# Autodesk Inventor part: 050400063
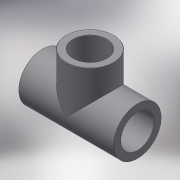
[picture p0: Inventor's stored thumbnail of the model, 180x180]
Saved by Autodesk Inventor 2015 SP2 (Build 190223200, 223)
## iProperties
Created: 2017-10
Part Number: 050400063
Material: Generic
Description: PLASSON TEE-CEMENT PVC 63
Document SubType Name: Modeling
Designer: KIM
Density: 1 g/cm^3
Appearance: Default
Author: KIM
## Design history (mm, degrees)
derived "050400.ipt"
feature "Solid1::050400.ipt"
feature "Solid2::050400.ipt"
tag "TaggingFeature1"
body "Solid1"
other parameters: "d0" = 145, "d1" = 73, "d2" = 38, "d4" = 63, "d5" = 56.7, "d7" = 0.63, "d8" = 38, "d9" = 73, "d10" = 73, "d11" = 63, "d12" = 56.7, "d15" = 0, "d17" = 0, "d18" = 63, "d19" = 56.7, "d20" = 63, "d21" = 38, "d22" = 0, "d23" = 38, "d24" = 0.63, "d_" = 63, "E_" = 73, "H_" = 145, "l_" = 38, "Z_" = 35
